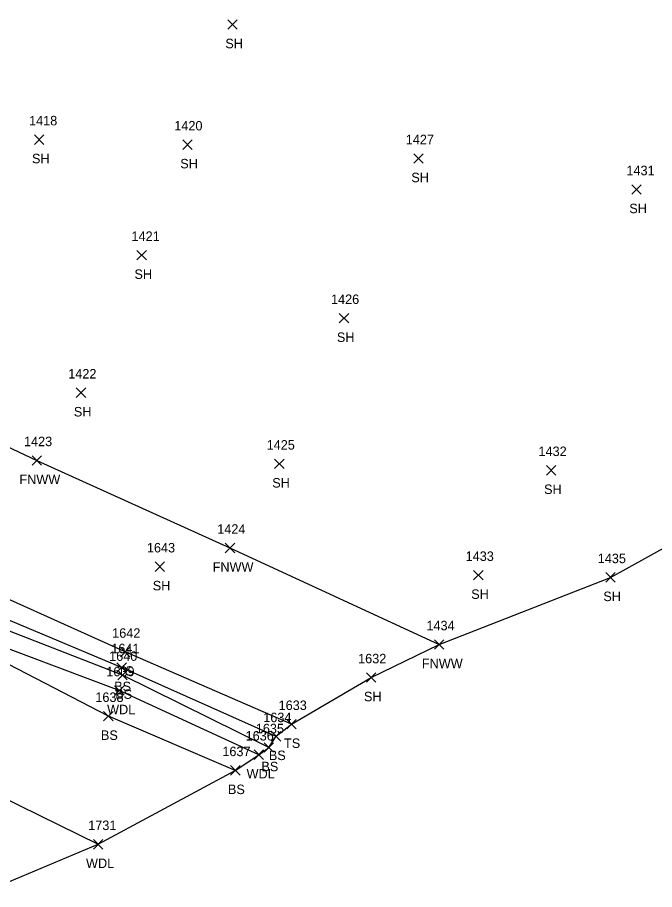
# Model space of a CAD drawing. Extents: x 1599569 to 1610055, y 642560 to 647860.
# Drawn here: x 1602129.4 to 1602263.8, y 647113 to 647296.9 of the extents above; entities that cross this region are included whole.
import ezdxf

# ---------------------------------------------------------------- set-up
doc = ezdxf.new("R2010")
doc.units = 0
for name, color, linetype in [('L_A', 7, 'Continuous'), ('L_I', 7, 'Continuous'), ('L_TIC', 7, 'Continuous'), ('LAWA', 7, 'Continuous'), ('LELB', 7, 'Continuous'), ('LFNC', 7, 'Continuous'), ('LSOGP', 7, 'Continuous')]:
    doc.layers.add(name, color=color, linetype=linetype)

msp = doc.modelspace()

# ---------------------------------------------------------------- linework, layer by layer
at = {"layer": 'L_TIC'}
for points in [[(1602173.77, 647294.39), (1602175.77, 647296.39)], [(1602175.77, 647294.39), (1602173.77, 647296.39)], [(1602132.96, 647270.13), (1602134.96, 647272.13)], [(1602134.96, 647270.13), (1602132.96, 647272.13)], [(1602164.26, 647269.06), (1602166.26, 647271.06)], [(1602166.26, 647269.06), (1602164.26, 647271.06)], [(1602213.01, 647266.15), (1602215.01, 647268.15)], [(1602215.01, 647266.15), (1602213.01, 647268.15)], [(1602259.01, 647259.62), (1602261.01, 647261.62)], [(1602261.01, 647259.62), (1602259.01, 647261.62)], [(1602154.58, 647245.76), (1602156.58, 647247.76)], [(1602156.58, 647245.76), (1602154.58, 647247.76)], [(1602197.3, 647232.47), (1602199.3, 647234.47)], [(1602199.3, 647232.47), (1602197.3, 647234.47)], [(1602141.79, 647216.76), (1602143.79, 647218.76)], [(1602143.79, 647216.76), (1602141.79, 647218.76)], [(1602132.46, 647202.49), (1602134.46, 647204.49)], [(1602134.46, 647202.49), (1602132.46, 647204.49)], [(1602183.66, 647201.77), (1602185.66, 647203.77)], [(1602185.66, 647201.77), (1602183.66, 647203.77)], [(1602241.03, 647200.41), (1602243.03, 647202.41)], [(1602243.03, 647200.41), (1602241.03, 647202.41)], [(1602173.23, 647184.03), (1602175.23, 647186.03)], [(1602175.23, 647184.03), (1602173.23, 647186.03)], [(1602158.44, 647180.09), (1602160.44, 647182.09)], [(1602160.44, 647180.09), (1602158.44, 647182.09)], [(1602225.65, 647178.3), (1602227.65, 647180.3)], [(1602227.65, 647178.3), (1602225.65, 647180.3)], [(1602253.53, 647177.83), (1602255.53, 647179.83)], [(1602255.53, 647177.83), (1602253.53, 647179.83)], [(1602217.38, 647163.67), (1602219.38, 647165.67)], [(1602219.38, 647163.67), (1602217.38, 647165.67)], [(1602151.11, 647162.1), (1602153.11, 647164.1)], [(1602153.11, 647162.1), (1602151.11, 647164.1)], [(1602150.36, 647158.84), (1602152.36, 647160.84)], [(1602152.36, 647158.84), (1602150.36, 647160.84)], [(1602150.56, 647157.23), (1602152.56, 647159.23)], [(1602152.56, 647157.23), (1602150.56, 647159.23)], [(1602203.01, 647156.71), (1602205.01, 647158.71)], [(1602205.01, 647156.71), (1602203.01, 647158.71)], [(1602149.88, 647153.98), (1602151.88, 647155.98)], [(1602151.88, 647153.98), (1602149.88, 647155.98)], [(1602147.56, 647148.57), (1602149.56, 647150.57)], [(1602149.56, 647148.57), (1602147.56, 647150.57)], [(1602186.23, 647146.87), (1602188.23, 647148.87)], [(1602188.23, 647146.87), (1602186.23, 647148.87)], [(1602182.99, 647144.31), (1602184.99, 647146.31)], [(1602184.99, 647144.31), (1602182.99, 647146.31)], [(1602179.33, 647140.44), (1602181.33, 647142.44)], [(1602181.33, 647140.44), (1602179.33, 647142.44)], [(1602181.42, 647141.96), (1602183.42, 647143.96)], [(1602183.42, 647141.96), (1602181.42, 647143.96)], [(1602174.36, 647137.14), (1602176.36, 647139.14)], [(1602176.36, 647137.14), (1602174.36, 647139.14)], [(1602145.43, 647121.56), (1602147.43, 647123.56)], [(1602147.43, 647121.56), (1602145.43, 647123.56)]]:
    msp.add_lwpolyline(points, dxfattribs=at)
at = {"layer": 'LAWA'}
msp.add_lwpolyline([(1602180.33, 647141.44), (1602150.88, 647154.98), (1602104.39, 647172.42), (1602082.56, 647185.2), (1602043.45, 647201.75), (1602008.28, 647219.45), (1601966.23, 647235.49), (1601948.97, 647234.83), (1601926.45, 647244.69), (1601913.4, 647251.3), (1601888.48, 647252.71), (1601887.89, 647249.04), (1601886.74, 647233.29), (1601929.19, 647212.47), (1601953.03, 647205.71), (1601992.78, 647195.01), (1602016.34, 647184.99), (1602055.62, 647163.31), (1602090.65, 647150.16), (1602117.28, 647136.84), (1602146.43, 647122.56)], dxfattribs=at)
at = {"layer": 'LELB'}
for points in [[(1602187.23, 647147.87), (1602152.11, 647163.1), (1602114.3, 647180.14), (1602085.42, 647192.28), (1602045.9, 647209.48), (1602010.38, 647226.8), (1601969.76, 647249.48), (1601957.16, 647252.14), (1601944.12, 647254.48), (1601933.71, 647251.66), (1601931.49, 647247.11)], [(1602183.99, 647145.31), (1602151.36, 647159.84), (1602109.74, 647177.25), (1602084.28, 647188.71), (1602045.93, 647206.07), (1602009.3, 647224.02), (1601966.2, 647243.2), (1601950.47, 647247.44), (1601940.33, 647248.53), (1601931.49, 647247.11)], [(1602182.42, 647142.96), (1602151.56, 647158.23), (1602106.3, 647175.81), (1602083.94, 647187.65), (1602045.25, 647204.44), (1602009.04, 647222.19), (1601965.15, 647239.88), (1601948.92, 647245.15), (1601941.5, 647243.9), (1601938.04, 647244.79), (1601931.49, 647247.11)], [(1602175.36, 647138.14), (1602148.56, 647149.57), (1602104.39, 647172.42)]]:
    msp.add_lwpolyline(points, dxfattribs=at)
at = {"layer": 'LFNC'}
msp.add_lwpolyline([(1601805.75, 647315.97), (1601814.87, 647313.37), (1601838.01, 647307.85), (1601857.39, 647303.37), (1601875.37, 647298.23), (1601909.67, 647289.73), (1601944.01, 647280.41), (1601968.24, 647274.13), (1601982.37, 647269.76), (1602013.8, 647257.69), (1602065.95, 647235.95), (1602107.23, 647215.87), (1602133.46, 647203.49), (1602174.23, 647185.03), (1602218.38, 647164.67)], dxfattribs=at)
at = {"layer": 'LSOGP'}
msp.add_lwpolyline([(1602123.65, 647113.01), (1602146.44, 647122.57), (1602175.36, 647138.14), (1602180.33, 647141.45), (1602182.42, 647142.96), (1602183.99, 647145.32), (1602187.22, 647147.87), (1602204.01, 647157.72), (1602218.38, 647164.67), (1602254.53, 647178.83), (1602291.22, 647199.13)], dxfattribs=at)

# ---------------------------------------------------------------- texts
at = {"layer": 'L_A'}
for s, p in [('SH', (1602173.25, 647290.39)), ('SH', (1602132.45, 647266.13)), ('SH', (1602163.74, 647265.06)), ('SH', (1602212.5, 647262.15)), ('SH', (1602258.5, 647255.62)), ('SH', (1602154.07, 647241.76)), ('SH', (1602196.79, 647228.47)), ('SH', (1602141.28, 647212.76)), ('FNWW', (1602129.8, 647198.49)), ('SH', (1602183.15, 647197.77)), ('SH', (1602240.52, 647196.41)), ('FNWW', (1602170.58, 647180.03)), ('SH', (1602157.93, 647176.09)), ('SH', (1602225.14, 647174.3)), ('SH', (1602253.02, 647173.83)), ('FNWW', (1602214.73, 647159.67)), ('TS', (1602150.52, 647158.1)), ('BS', (1602149.8, 647154.84)), ('BS', (1602150, 647153.23)), ('SH', (1602202.5, 647152.71)), ('WDL', (1602148.3, 647149.98)), ('BS', (1602147, 647144.57)), ('TS', (1602185.64, 647142.87)), ('BS', (1602182.43, 647140.31)), ('BS', (1602180.86, 647137.96)), ('WDL', (1602177.74, 647136.44)), ('BS', (1602173.8, 647133.14)), ('WDL', (1602143.85, 647117.56))]:
    msp.add_text(s, height=2, dxfattribs=at).set_placement(p)
at = {"layer": 'L_I'}
for s, p in [('1418', (1602131.83, 647274.13)), ('1420', (1602162.48, 647273.06)), ('1427', (1602211.32, 647270.15)), ('1431', (1602257.89, 647263.62)), ('1421', (1602153.45, 647249.76)), ('1426', (1602195.55, 647236.47)), ('1422', (1602140.1, 647220.76)), ('1423', (1602130.76, 647206.49)), ('1425', (1602181.97, 647205.77)), ('1432', (1602239.34, 647204.41)), ('1424', (1602171.54, 647188.03)), ('1643', (1602156.7, 647184.09)), ('1433', (1602223.96, 647182.3)), ('1435', (1602251.84, 647181.83)), ('1642', (1602149.37, 647166.1)), ('1434', (1602215.69, 647167.67)), ('1641', (1602149.18, 647162.84)), ('1640', (1602148.73, 647161.23)), ('1632', (1602201.27, 647160.71)), ('1639', (1602148.13, 647157.98)), ('1638', (1602145.82, 647152.57)), ('1633', (1602184.49, 647150.87)), ('1634', (1602181.25, 647148.31)), ('1635', (1602179.68, 647145.96)), ('1636', (1602177.53, 647144.44)), ('1637', (1602172.62, 647141.14)), ('1731', (1602144.31, 647125.56))]:
    msp.add_text(s, height=2, dxfattribs=at).set_placement(p)

doc.saveas('drawing.dxf')
